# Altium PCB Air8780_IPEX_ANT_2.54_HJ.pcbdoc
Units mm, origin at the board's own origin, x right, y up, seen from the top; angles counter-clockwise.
Board outline 52.7 x 68.7 mm, 2 copper layers (Top Layer, Bottom Layer); 1 components, 0 nets, 36 pads, 0 vias.
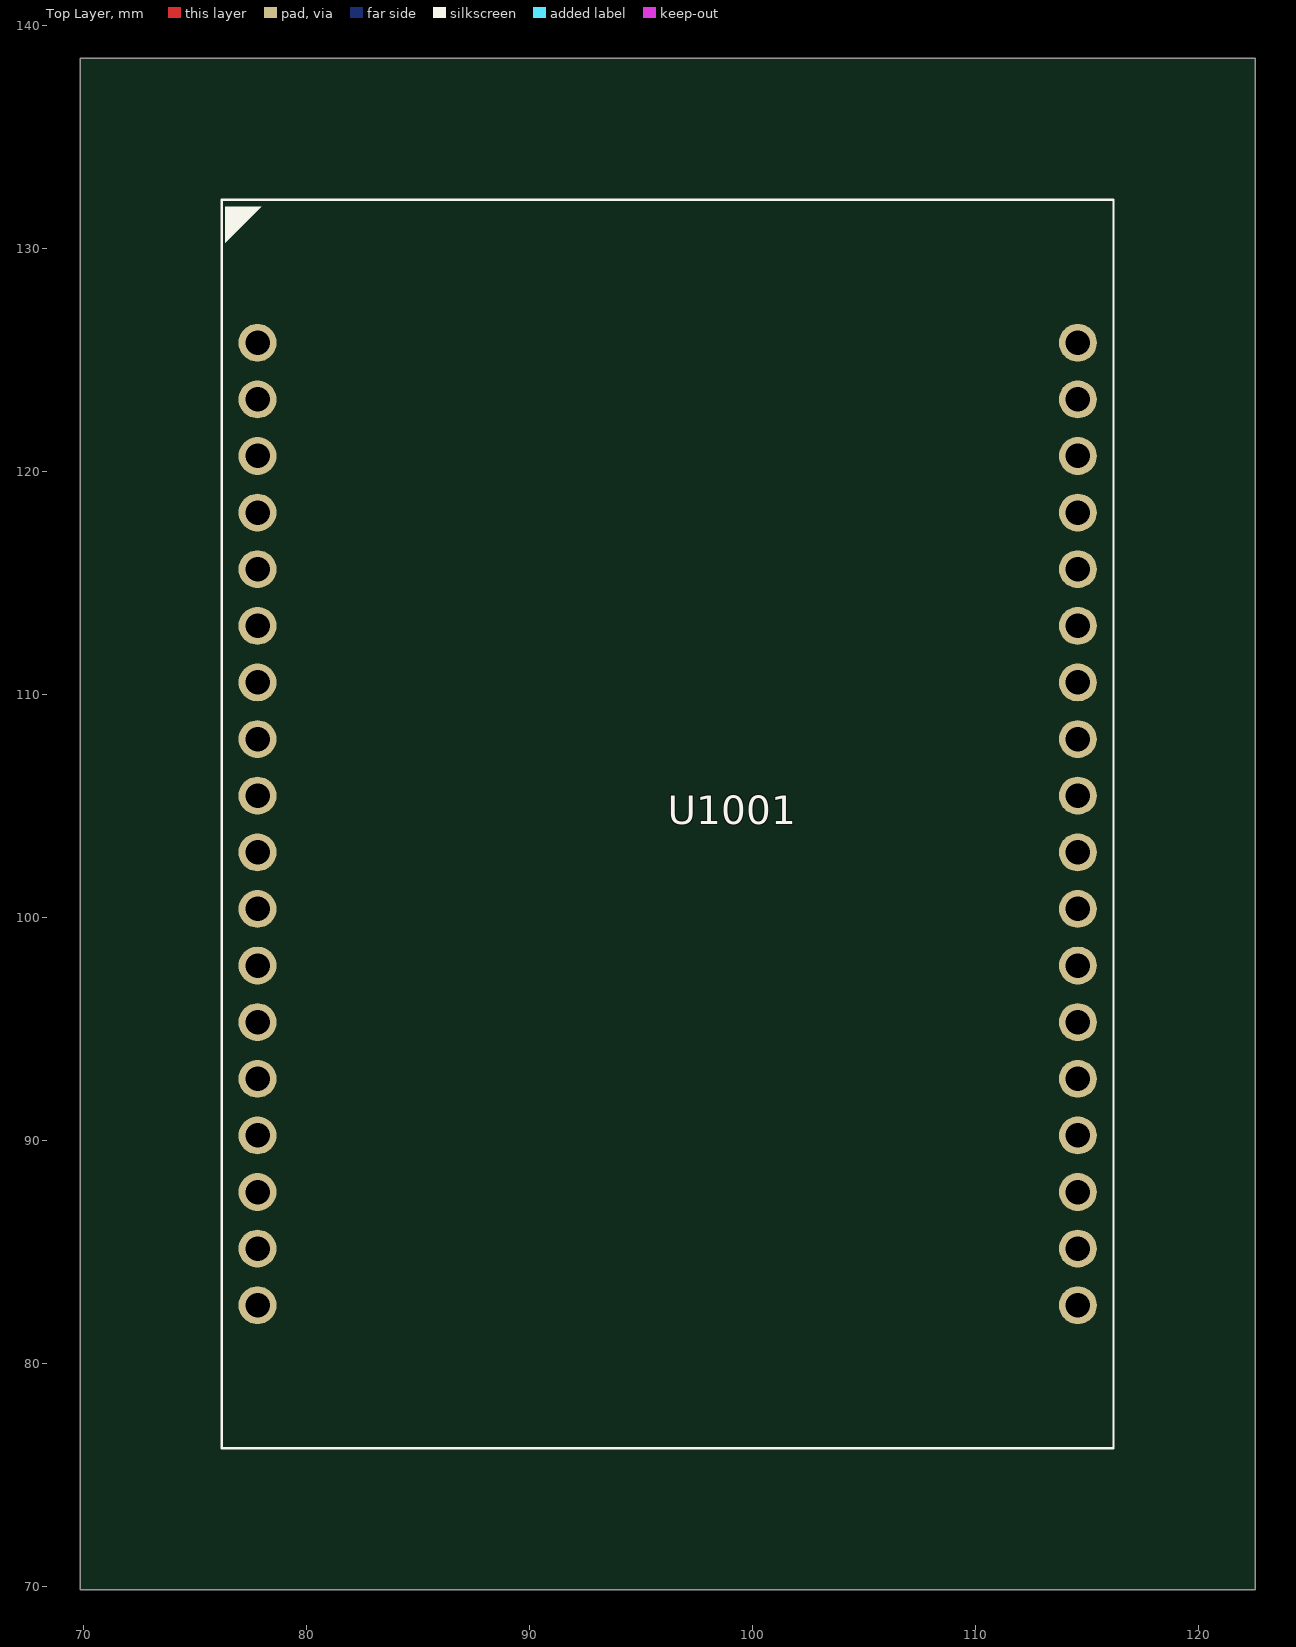
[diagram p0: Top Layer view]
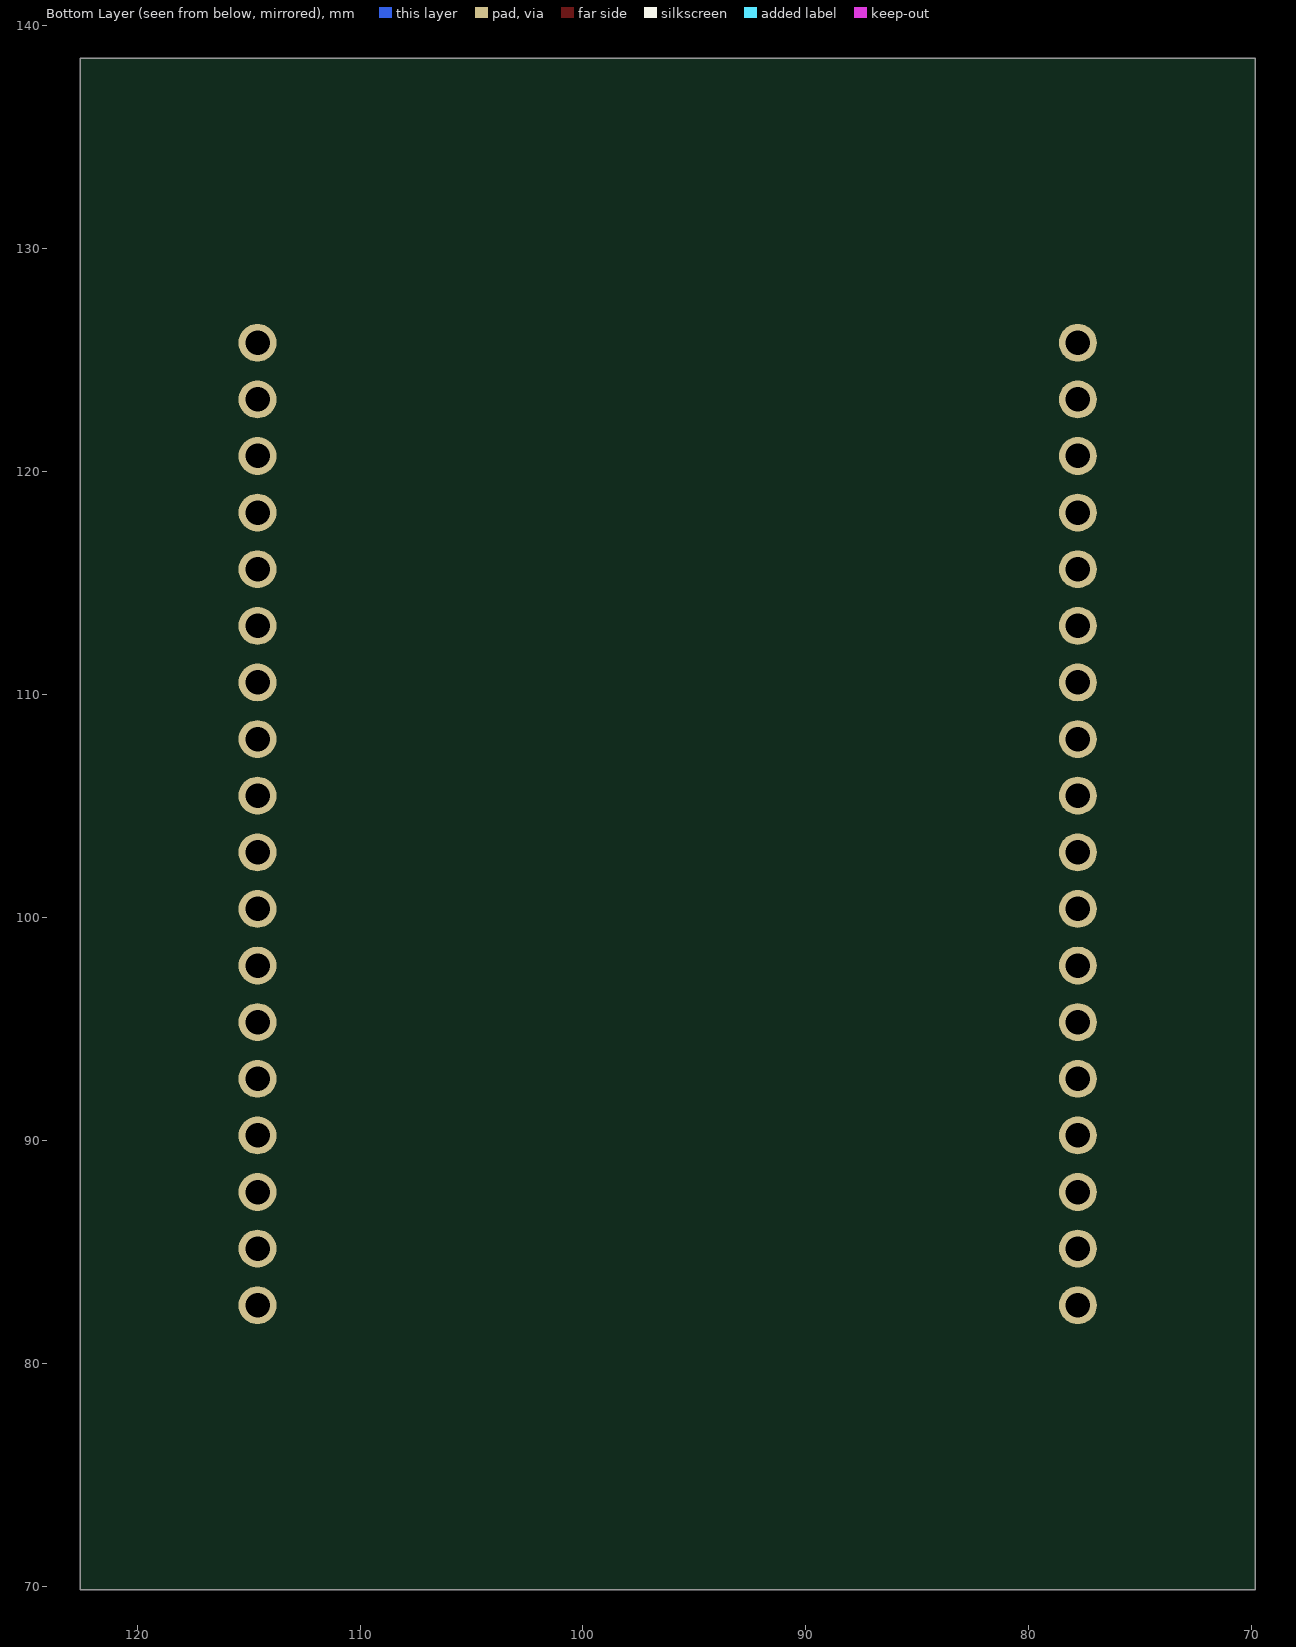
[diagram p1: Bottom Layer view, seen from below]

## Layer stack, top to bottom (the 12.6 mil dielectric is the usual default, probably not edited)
Top Layer: signal copper (thickness not stored)
Dielectric: dielectric 0.32, FR-4, Dk 4.8
Bottom Layer: signal copper (thickness not stored)

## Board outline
122.55,69.85 69.85,69.85 69.85,138.55 122.55,138.55

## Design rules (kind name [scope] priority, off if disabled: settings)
BoardOutlineClearance safeClearance [All] p0: genericclearance=0.254 ignorepadtopadclearanceinfootprint=FALSE except(0: Region-OutlineEdge Poly-OutlineEdge Text-OutlineEdge Sheet-OutlineEdge Hole-OutlineEdge Track-CutoutEdge SMDPad-CutoutEdge THPad-CutoutEdge Via-CutoutEdge Fill-CutoutEdge Region-CutoutEdge Poly-CutoutEdge Text-CutoutEdge Sheet-CutoutEdge Hole-CutoutEdge Arc-SplitContinuation Track-SplitContinuation SMDPad-SplitContinuation THPad-SplitContinuation Via-SplitContinuation Fill-SplitContinuation Poly-SplitContinuation Region-SplitContinuation Text-SplitContinuation; 0.152: Track-OutlineEdge SMDPad-OutlineEdge THPad-OutlineEdge Via-OutlineEdge Fill-OutlineEdge)
Clearance safeClearance [All] p1: gap=0.178 ignorepadtopadclearanceinfootprint=FALSE except(0: Region-Track Poly-Track Region-SMDPad Poly-SMDPad Region-THPad Poly-THPad Region-Via Poly-Via Region-Fill Poly-Fill Text-Fill Track-Region SMDPad-Region THPad-Region Via-Region Fill-Region Region-Region Poly-Region Text-Region Sheet-Region Hole-Region Track-Poly SMDPad-Poly THPad-Poly Via-Poly Fill-Poly Region-Poly Poly-Poly Text-Poly Sheet-Poly Hole-Poly Fill-Text Region-Text Poly-Text Text-Text Sheet-Text Hole-Text Region-Sheet Poly-Sheet Text-Sheet Sheet-Sheet Hole-Sheet Region-Hole Poly-Hole Text-Hole Sheet-Hole; 0.152: Track-Track SMDPad-Track THPad-Track Via-Track Fill-Track Text-Track Sheet-Track Hole-Track Track-SMDPad SMDPad-SMDPad THPad-SMDPad Via-SMDPad Fill-SMDPad Text-SMDPad Sheet-SMDPad Hole-SMDPad Track-THPad SMDPad-THPad THPad-THPad Via-THPad Fill-THPad Text-THPad Sheet-THPad Hole-THPad Track-Via SMDPad-Via THPad-Via Via-Via Fill-Via Text-Via Sheet-Via Hole-Via Track-Fill SMDPad-Fill THPad-Fill Via-Fill Fill-Fill Sheet-Fill Hole-Fill Track-Text SMDPad-Text THPad-Text Via-Text Track-Sheet SMDPad-Sheet THPad-Sheet Via-Sheet Fill-Sheet Track-Hole SMDPad-Hole THPad-Hole Via-Hole Fill-Hole Hole-Hole)
PasteMaskExpansion Common [All] p1: expansion=0
SolderMaskExpansion Common [All] p1: useseparateexpansions=TRUE expansion=0 expansionbottom=0
Width trackWidth [All] p1: maxlimit=12 minlimit=12 preferedwidth=12

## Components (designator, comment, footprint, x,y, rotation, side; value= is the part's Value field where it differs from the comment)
U1001 "AIR8780_IPEX_ANT_2.54" AIR8780_2.54_HJ 96.2,104.2 r0 top

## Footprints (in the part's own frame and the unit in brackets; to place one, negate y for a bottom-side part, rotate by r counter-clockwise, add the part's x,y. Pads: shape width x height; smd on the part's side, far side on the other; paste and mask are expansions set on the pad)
AIR8780_2.54_HJ [mm]
  round 1.7 hole 1.1: 1(-18.4,21.59) 2(-18.4,19.05) 3(-18.4,16.51) 4(-18.4,13.97) 5(-18.4,11.43) 6(-18.4,8.89) 7(-18.4,6.35) 8(-18.4,3.81) 9(-18.4,1.27) 10(-18.4,-1.27) 11(-18.4,-3.81) 12(-18.4,-6.35) 13(-18.4,-8.89) 14(-18.4,-11.43) 15(-18.4,-13.97) 16(-18.4,-16.51) 17(-18.4,-19.05) 18(-18.4,-21.59) 19(18.4,-21.59) 20(18.4,-19.05) 21(18.4,-16.51) 22(18.4,-13.97) 23(18.4,-11.43) 24(18.4,-8.89) 25(18.4,-6.35) 26(18.4,-3.81) 27(18.4,-1.27) 28(18.4,1.27) 29(18.4,3.81) 30(18.4,6.35) 31(18.4,8.89) 32(18.4,11.43) 33(18.4,13.97) 34(18.4,16.51) 35(18.4,19.05) 36(18.4,21.59)
  silkscreen extent -20,-28 20,28

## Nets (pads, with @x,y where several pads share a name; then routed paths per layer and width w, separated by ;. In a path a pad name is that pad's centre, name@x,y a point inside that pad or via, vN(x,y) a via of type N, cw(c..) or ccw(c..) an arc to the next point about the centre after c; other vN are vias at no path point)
pads on no net: U1001.1 U1001.2 U1001.3 U1001.4 U1001.5 U1001.6 U1001.7 U1001.8 U1001.9 U1001.10 U1001.11 U1001.12 U1001.13 U1001.14 U1001.15 U1001.16 U1001.17 U1001.18 U1001.19 U1001.20 U1001.21 U1001.22 U1001.23 U1001.24 U1001.25 U1001.26 U1001.27 U1001.28 U1001.29 U1001.30 U1001.31 U1001.32 U1001.33 U1001.34 U1001.35 U1001.36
